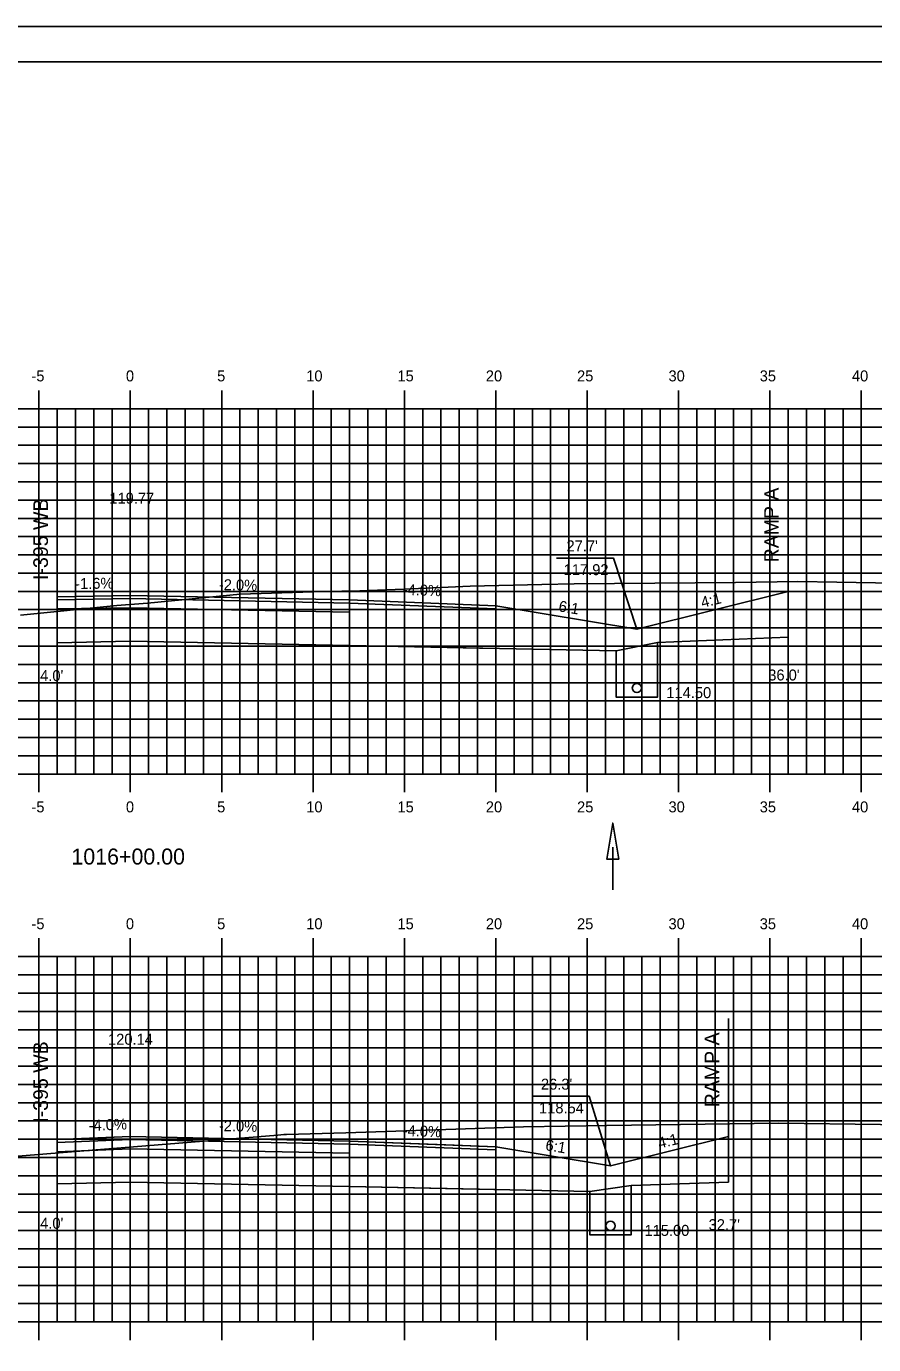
# Model space of a CAD drawing. Extents: x 853069 to 853241, y 365624 to 365734.
# Drawn here: x 853146.4 to 853192.7, y 365661.8 to 365734 of the extents above; entities that cross this region are included whole.
import ezdxf

# ---------------------------------------------------------------- set-up
doc = ezdxf.new("R2010")
doc.units = 0
for name, color, linetype in [('ANNOTATION', 7, 'Continuous'), ('BORDER', 7, 'Continuous'), ('D_Drainage_Ditch_Line', 7, 'Continuous'), ('D_Roadway_Centerline', 7, 'Continuous'), ('D_Roadway_Centerline_Text', 7, 'Continuous'), ('D_Roadway_Edge_Shoulder', 7, 'Continuous'), ('D_Roadway_Edge_TW', 7, 'Continuous'), ('D_Roadway_FinishedGrade', 7, 'Continuous'), ('D_Roadway_Pavement', 7, 'Continuous'), ('D_Roadway_SubGrade', 7, 'Continuous'), ('D_Text_Standard', 7, 'Continuous'), ('Default', 7, 'Continuous'), ('H_V ANNOTATION', 7, 'Continuous'), ('M_Roadway_Centerline', 7, 'Continuous'), ('MAJOR', 7, 'Continuous'), ('MINOR', 7, 'Continuous'), ('PDRAIN', 7, 'Continuous'), ('PLOT BOUNDARY', 7, 'Continuous'), ('S_Roadway_Centerline', 7, 'Continuous')]:
    doc.layers.add(name, color=color, linetype=linetype)

msp = doc.modelspace()

# ---------------------------------------------------------------- linework, layer by layer
at = {"layer": 'ANNOTATION'}
for p, q in [((853188.055, 365703.013), (853188.055, 365700.513)), ((853164.061, 365700.058), (853178.656, 365699.766))]:
    msp.add_line(p, q, dxfattribs=at)
for points in [[(853175.386, 365704.854), (853178.496, 365704.854), (853179.781, 365700.951)], [(853188.055, 365700.513), (853180.906, 365700.229)], [(853174.056, 365675.38), (853177.166, 365675.38), (853178.339, 365671.564)]]:
    msp.add_lwpolyline(points, dxfattribs=at)
at = {"layer": 'BORDER'}
msp.add_lwpolyline([(853077.062, 365627.027), (853237.062, 365627.027), (853237.062, 365732.027), (853077.062, 365732.027)], close=True, dxfattribs=at)
at = {"layer": 'D_Drainage_Ditch_Line'}
msp.add_line((853178.463, 365689.027), (853178.463, 365686.678), dxfattribs=at)
msp.add_lwpolyline([(853178.791, 365688.371), (853178.135, 365688.371), (853178.463, 365690.339)], close=True, dxfattribs=at)
at = {"layer": 'D_Roadway_Centerline'}
for p, q in [((853178.656, 365699.766), (853180.906, 365700.229)), ((853164.061, 365670.431), (853177.214, 365670.168)), ((853177.214, 365670.168), (853179.464, 365670.501))]:
    msp.add_line(p, q, dxfattribs=at)
for points in [[(853172.061, 365702.238), (853179.781, 365700.951), (853188.061, 365703.014)], [(853148.061, 365673.011), (853149.892, 365673.084), (853152.061, 365673.171), (853164.06, 365672.931), (853164.061, 365672.931), (853169.328, 365672.72), (853172.061, 365672.611)], [(853172.061, 365672.611), (853178.339, 365671.564), (853184.796, 365673.174)], [(853184.796, 365670.675), (853179.464, 365670.501)]]:
    msp.add_lwpolyline(points, dxfattribs=at)
at = {"layer": 'D_Roadway_Edge_Shoulder'}
for points in [[(853152.061, 365702.798), (853148.061, 365702.734), (853148.061, 365702.567), (853152.061, 365702.631)], [(853164.061, 365702.558), (853172.061, 365702.238), (853172.061, 365702.071), (853164.061, 365702.391)], [(853152.061, 365673.171), (853148.061, 365673.011), (853148.061, 365672.845), (853152.061, 365673.005)], [(853164.061, 365672.931), (853172.061, 365672.611), (853172.061, 365672.445), (853164.061, 365672.765)]]:
    msp.add_lwpolyline(points, close=True, dxfattribs=at)
at = {"layer": 'D_Roadway_Edge_TW'}
for points in [[(853152.061, 365702.798), (853164.061, 365702.558), (853164.061, 365702.391), (853152.061, 365702.631)], [(853152.061, 365673.171), (853164.061, 365672.931), (853164.061, 365672.765), (853152.061, 365673.005)]]:
    msp.add_lwpolyline(points, close=True, dxfattribs=at)
for points in [[(853164.061, 365702.558), (853164.061, 365702.391)], [(853164.061, 365672.931), (853164.061, 365672.765)]]:
    msp.add_lwpolyline(points, dxfattribs=at)
at = {"layer": 'D_Roadway_FinishedGrade'}
for p, q in [((853152.061, 365702.798), (853152.061, 365702.548)), ((853148.061, 365702.734), (853148.061, 365702.484)), ((853164.061, 365702.558), (853164.061, 365702.308)), ((853172.061, 365702.238), (853172.061, 365701.988)), ((853152.061, 365673.171), (853152.061, 365672.921)), ((853148.061, 365673.011), (853148.061, 365672.761)), ((853164.06, 365672.931), (853164.06, 365672.681)), ((853172.061, 365672.611), (853172.061, 365672.361))]:
    msp.add_line(p, q, dxfattribs=at)
at = {"layer": 'D_Roadway_Pavement'}
for points in [[(853152.061, 365702.631), (853148.061, 365702.567), (853148.061, 365702.067), (853152.061, 365702.131)], [(853152.061, 365702.631), (853164.061, 365702.391), (853164.061, 365701.891), (853152.061, 365702.131)], [(853152.061, 365673.005), (853148.061, 365672.845), (853148.061, 365672.345), (853152.061, 365672.505)], [(853152.061, 365673.005), (853164.061, 365672.765), (853164.061, 365672.265), (853152.061, 365672.505)]]:
    msp.add_lwpolyline(points, close=True, dxfattribs=at)
for points in [[(853164.061, 365702.391), (853164.061, 365701.891)], [(853164.061, 365702.391), (853164.061, 365701.891)], [(853164.061, 365672.765), (853164.061, 365672.265)], [(853164.061, 365672.765), (853164.061, 365672.265)]]:
    msp.add_lwpolyline(points, dxfattribs=at)
at = {"layer": 'D_Roadway_SubGrade'}
for p, q in [((853188.055, 365709.475), (853188.055, 365700.513)), ((853148.061, 365708.638), (853148.061, 365700.218)), ((853184.796, 365679.636), (853184.796, 365670.675)), ((853148.061, 365678.915), (853148.061, 365670.591))]:
    msp.add_line(p, q, dxfattribs=at)
for points in [[(853152.061, 365702.131), (853148.061, 365702.067), (853148.061, 365702.567), (853148.061, 365702.734), (853148.061, 365700.218), (853152.061, 365700.298)], [(853152.061, 365702.131), (853164.061, 365701.891), (853164.061, 365700.058), (853152.061, 365700.298)], [(853164.061, 365701.891), (853164.061, 365702.391), (853172.061, 365702.071), (853172.061, 365702.238), (853172.061, 365699.898), (853164.061, 365700.058)], [(853152.061, 365672.505), (853148.061, 365672.345), (853148.061, 365672.845), (853148.061, 365673.011), (853148.061, 365670.591), (853152.061, 365670.671)], [(853152.061, 365672.505), (853164.061, 365672.265), (853164.061, 365670.431), (853152.061, 365670.671)], [(853164.061, 365672.265), (853164.061, 365672.765), (853172.061, 365672.445), (853172.061, 365672.611), (853172.061, 365670.271), (853164.061, 365670.431)]]:
    msp.add_lwpolyline(points, close=True, dxfattribs=at)
for points in [[(853164.061, 365701.891), (853164.061, 365700.058)], [(853164.061, 365672.265), (853164.061, 365670.431)]]:
    msp.add_lwpolyline(points, dxfattribs=at)
at = {"layer": 'Default'}
msp.add_line((853184.796, 365673.175), (853184.796, 365670.675), dxfattribs=at)
for points in [[(853172.061, 365672.611), (853178.339, 365671.564)], [(853184.796, 365670.675), (853179.464, 365670.501)]]:
    msp.add_lwpolyline(points, dxfattribs=at)
at = {"layer": 'MAJOR'}
for p, q in [((853147.061, 365714.029), (853147.061, 365713.027)), ((853152.061, 365714.029), (853152.061, 365713.027)), ((853157.061, 365714.029), (853157.061, 365713.027)), ((853162.061, 365714.029), (853162.061, 365713.027)), ((853167.061, 365714.029), (853167.061, 365713.027)), ((853172.061, 365714.029), (853172.061, 365713.027)), ((853177.061, 365714.029), (853177.061, 365713.027)), ((853182.061, 365714.029), (853182.061, 365713.027)), ((853187.061, 365714.029), (853187.061, 365713.027)), ((853192.061, 365714.029), (853192.061, 365713.027)), ((853082.061, 365713.027), (853222.061, 365713.027)), ((853082.061, 365713.027), (853222.061, 365713.027)), ((853147.061, 365693.027), (853147.061, 365713.027)), ((853152.061, 365693.027), (853152.061, 365713.027)), ((853157.061, 365693.027), (853157.061, 365713.027)), ((853162.061, 365693.027), (853162.061, 365713.027)), ((853167.061, 365693.027), (853167.061, 365713.027)), ((853172.061, 365693.027), (853172.061, 365713.027)), ((853177.061, 365693.027), (853177.061, 365713.027)), ((853182.061, 365693.027), (853182.061, 365713.027)), ((853187.061, 365693.027), (853187.061, 365713.027)), ((853192.061, 365693.027), (853192.061, 365713.027)), ((853082.061, 365708.027), (853222.061, 365708.027)), ((853082.061, 365703.027), (853222.061, 365703.027)), ((853082.061, 365698.027), (853222.061, 365698.027)), ((853082.061, 365693.027), (853222.061, 365693.027)), ((853082.061, 365693.027), (853222.061, 365693.027)), ((853147.061, 365692.025), (853147.061, 365693.027)), ((853152.061, 365692.025), (853152.061, 365693.027)), ((853157.061, 365692.025), (853157.061, 365693.027)), ((853162.061, 365692.025), (853162.061, 365693.027)), ((853167.061, 365692.025), (853167.061, 365693.027)), ((853172.061, 365692.025), (853172.061, 365693.027)), ((853177.061, 365692.025), (853177.061, 365693.027)), ((853182.061, 365692.025), (853182.061, 365693.027)), ((853187.061, 365692.025), (853187.061, 365693.027)), ((853192.061, 365692.025), (853192.061, 365693.027)), ((853147.061, 365684.029), (853147.061, 365683.027)), ((853152.061, 365684.029), (853152.061, 365683.027)), ((853157.061, 365684.029), (853157.061, 365683.027)), ((853162.061, 365684.029), (853162.061, 365683.027)), ((853167.061, 365684.029), (853167.061, 365683.027)), ((853172.061, 365684.029), (853172.061, 365683.027)), ((853177.061, 365684.029), (853177.061, 365683.027)), ((853182.061, 365684.029), (853182.061, 365683.027)), ((853187.061, 365684.029), (853187.061, 365683.027)), ((853192.061, 365684.029), (853192.061, 365683.027)), ((853082.061, 365683.027), (853222.061, 365683.027)), ((853082.061, 365683.027), (853222.061, 365683.027)), ((853147.061, 365663.027), (853147.061, 365683.027)), ((853152.061, 365663.027), (853152.061, 365683.027)), ((853157.061, 365663.027), (853157.061, 365683.027)), ((853162.061, 365663.027), (853162.061, 365683.027)), ((853167.061, 365663.027), (853167.061, 365683.027)), ((853172.061, 365663.027), (853172.061, 365683.027)), ((853177.061, 365663.027), (853177.061, 365683.027)), ((853182.061, 365663.027), (853182.061, 365683.027)), ((853187.061, 365663.027), (853187.061, 365683.027)), ((853192.061, 365663.027), (853192.061, 365683.027)), ((853082.061, 365678.027), (853222.061, 365678.027)), ((853082.061, 365673.027), (853222.061, 365673.027)), ((853082.061, 365668.027), (853222.061, 365668.027)), ((853082.061, 365663.027), (853222.061, 365663.027)), ((853082.061, 365663.027), (853222.061, 365663.027)), ((853147.061, 365662.025), (853147.061, 365663.027)), ((853152.061, 365662.025), (853152.061, 365663.027)), ((853157.061, 365662.025), (853157.061, 365663.027)), ((853162.061, 365662.025), (853162.061, 365663.027)), ((853167.061, 365662.025), (853167.061, 365663.027)), ((853172.061, 365662.025), (853172.061, 365663.027)), ((853177.061, 365662.025), (853177.061, 365663.027)), ((853182.061, 365662.025), (853182.061, 365663.027)), ((853187.061, 365662.025), (853187.061, 365663.027)), ((853192.061, 365662.025), (853192.061, 365663.027))]:
    msp.add_line(p, q, dxfattribs=at)
at = {"layer": 'MINOR'}
for p, q in [((853148.061, 365693.027), (853148.061, 365713.027)), ((853149.061, 365693.027), (853149.061, 365713.027)), ((853150.061, 365693.027), (853150.061, 365713.027)), ((853151.061, 365693.027), (853151.061, 365713.027)), ((853153.061, 365693.027), (853153.061, 365713.027)), ((853154.061, 365693.027), (853154.061, 365713.027)), ((853155.061, 365693.027), (853155.061, 365713.027)), ((853156.061, 365693.027), (853156.061, 365713.027)), ((853158.061, 365693.027), (853158.061, 365713.027)), ((853159.061, 365693.027), (853159.061, 365713.027)), ((853160.061, 365693.027), (853160.061, 365713.027)), ((853161.061, 365693.027), (853161.061, 365713.027)), ((853163.061, 365693.027), (853163.061, 365713.027)), ((853164.061, 365693.027), (853164.061, 365713.027)), ((853165.061, 365693.027), (853165.061, 365713.027)), ((853166.061, 365693.027), (853166.061, 365713.027)), ((853168.061, 365693.027), (853168.061, 365713.027)), ((853169.061, 365693.027), (853169.061, 365713.027)), ((853170.061, 365693.027), (853170.061, 365713.027)), ((853171.061, 365693.027), (853171.061, 365713.027)), ((853173.061, 365693.027), (853173.061, 365713.027)), ((853174.061, 365693.027), (853174.061, 365713.027)), ((853175.061, 365693.027), (853175.061, 365713.027)), ((853176.061, 365693.027), (853176.061, 365713.027)), ((853178.061, 365693.027), (853178.061, 365713.027)), ((853179.061, 365693.027), (853179.061, 365713.027)), ((853180.061, 365693.027), (853180.061, 365713.027)), ((853181.061, 365693.027), (853181.061, 365713.027)), ((853183.061, 365693.027), (853183.061, 365713.027)), ((853184.061, 365693.027), (853184.061, 365713.027)), ((853185.061, 365693.027), (853185.061, 365713.027)), ((853186.061, 365693.027), (853186.061, 365713.027)), ((853188.061, 365693.027), (853188.061, 365713.027)), ((853189.061, 365693.027), (853189.061, 365713.027)), ((853190.061, 365693.027), (853190.061, 365713.027)), ((853191.061, 365693.027), (853191.061, 365713.027)), ((853082.061, 365712.027), (853222.061, 365712.027)), ((853082.061, 365711.027), (853222.061, 365711.027)), ((853082.061, 365710.027), (853222.061, 365710.027)), ((853082.061, 365709.027), (853222.061, 365709.027)), ((853082.061, 365707.027), (853222.061, 365707.027)), ((853082.061, 365706.027), (853222.061, 365706.027)), ((853082.061, 365705.027), (853222.061, 365705.027)), ((853082.061, 365704.027), (853222.061, 365704.027)), ((853082.061, 365702.027), (853222.061, 365702.027)), ((853082.061, 365701.027), (853222.061, 365701.027)), ((853082.061, 365700.027), (853222.061, 365700.027)), ((853082.061, 365699.027), (853222.061, 365699.027)), ((853082.061, 365697.027), (853222.061, 365697.027)), ((853082.061, 365696.027), (853222.061, 365696.027)), ((853082.061, 365695.027), (853222.061, 365695.027)), ((853082.061, 365694.027), (853222.061, 365694.027)), ((853148.061, 365663.027), (853148.061, 365683.027)), ((853149.061, 365663.027), (853149.061, 365683.027)), ((853150.061, 365663.027), (853150.061, 365683.027)), ((853151.061, 365663.027), (853151.061, 365683.027)), ((853153.061, 365663.027), (853153.061, 365683.027)), ((853154.061, 365663.027), (853154.061, 365683.027)), ((853155.061, 365663.027), (853155.061, 365683.027)), ((853156.061, 365663.027), (853156.061, 365683.027)), ((853158.061, 365663.027), (853158.061, 365683.027)), ((853159.061, 365663.027), (853159.061, 365683.027)), ((853160.061, 365663.027), (853160.061, 365683.027)), ((853161.061, 365663.027), (853161.061, 365683.027)), ((853163.061, 365663.027), (853163.061, 365683.027)), ((853164.061, 365663.027), (853164.061, 365683.027)), ((853165.061, 365663.027), (853165.061, 365683.027)), ((853166.061, 365663.027), (853166.061, 365683.027)), ((853168.061, 365663.027), (853168.061, 365683.027)), ((853169.061, 365663.027), (853169.061, 365683.027)), ((853170.061, 365663.027), (853170.061, 365683.027)), ((853171.061, 365663.027), (853171.061, 365683.027)), ((853173.061, 365663.027), (853173.061, 365683.027)), ((853174.061, 365663.027), (853174.061, 365683.027)), ((853175.061, 365663.027), (853175.061, 365683.027)), ((853176.061, 365663.027), (853176.061, 365683.027)), ((853178.061, 365663.027), (853178.061, 365683.027)), ((853179.061, 365663.027), (853179.061, 365683.027)), ((853180.061, 365663.027), (853180.061, 365683.027)), ((853181.061, 365663.027), (853181.061, 365683.027)), ((853183.061, 365663.027), (853183.061, 365683.027)), ((853184.061, 365663.027), (853184.061, 365683.027)), ((853185.061, 365663.027), (853185.061, 365683.027)), ((853186.061, 365663.027), (853186.061, 365683.027)), ((853188.061, 365663.027), (853188.061, 365683.027)), ((853189.061, 365663.027), (853189.061, 365683.027)), ((853190.061, 365663.027), (853190.061, 365683.027)), ((853191.061, 365663.027), (853191.061, 365683.027)), ((853082.061, 365682.027), (853222.061, 365682.027)), ((853082.061, 365681.027), (853222.061, 365681.027)), ((853082.061, 365680.027), (853222.061, 365680.027)), ((853082.061, 365679.027), (853222.061, 365679.027)), ((853082.061, 365677.027), (853222.061, 365677.027)), ((853082.061, 365676.027), (853222.061, 365676.027)), ((853082.061, 365675.027), (853222.061, 365675.027)), ((853082.061, 365674.027), (853222.061, 365674.027)), ((853082.061, 365672.027), (853222.061, 365672.027)), ((853082.061, 365671.027), (853222.061, 365671.027)), ((853082.061, 365670.027), (853222.061, 365670.027)), ((853082.061, 365669.027), (853222.061, 365669.027)), ((853082.061, 365667.027), (853222.061, 365667.027)), ((853082.061, 365666.027), (853222.061, 365666.027)), ((853082.061, 365665.027), (853222.061, 365665.027)), ((853082.061, 365664.027), (853222.061, 365664.027))]:
    msp.add_line(p, q, dxfattribs=at)
at = {"layer": 'PDRAIN'}
for points in [[(853178.656, 365699.766), (853178.656, 365697.233), (853180.906, 365697.233), (853180.906, 365700.229)], [(853177.214, 365670.168), (853177.214, 365667.786), (853179.464, 365667.786), (853179.464, 365670.501)]]:
    msp.add_lwpolyline(points, dxfattribs=at)
for centre in [(853179.781, 365697.733), (853178.339, 365668.286)]:
    msp.add_circle(centre, 0.25, dxfattribs=at)
at = {"layer": 'PLOT BOUNDARY'}
msp.add_lwpolyline([(853068.968, 365623.968), (853238.968, 365623.968), (853238.968, 365733.968), (853068.968, 365733.968)], close=True, dxfattribs=at)
at = {"layer": 'S_Roadway_Centerline'}
for points in [[(853146.06, 365701.731), (853151.328, 365702.256), (853152.994, 365702.38), (853158.079, 365702.873), (853162.653, 365703.022), (853164.622, 365703.056), (853167.031, 365703.152), (853170.662, 365703.317), (853174.584, 365703.403), (853176.358, 365703.45), (853185.171, 365703.516), (853188.597, 365703.568), (853190.719, 365703.529), (853198.136, 365703.398), (853200.822, 365703.355), (853202.664, 365703.261), (853210.529, 365702.943), (853213.394, 365702.811), (853216.608, 365702.648), (853217.427, 365702.514), (853222.061, 365701.7)], [(853140.919, 365671.697), (853160.13, 365673.253), (853160.468, 365673.285), (853160.611, 365673.288), (853163.848, 365673.373), (853169.878, 365673.576), (853173.583, 365673.698), (853175.863, 365673.749), (853178.131, 365673.789), (853187.551, 365673.905), (853193.111, 365673.835), (853197.409, 365673.744), (853198.878, 365673.668), (853199.61, 365673.64), (853202.439, 365673.501), (853213.429, 365673.011), (853213.719, 365673.043), (853218.8, 365672.06), (853222.061, 365671.378)]]:
    msp.add_lwpolyline(points, dxfattribs=at)

# ---------------------------------------------------------------- texts
at = {"layer": 'ANNOTATION'}
for s, height, rotation, p in [('RAMP A', 0.8, 90, (853187.548, 365704.615)), ('I-395 WB', 0.8, 90, (853147.554, 365703.652)), ("27.7' ", 0.6, 360, (853175.93, 365705.217)), ('117.92', 0.6, 360, (853175.775, 365703.917)), ('-1.6%', 0.6, 0.91657, (853149.05, 365703.15)), ('-2.0%', 0.6, 358.85423, (853156.902, 365703.101)), ('-4.0%', 0.6, 357.70931, (853166.956, 365702.843)), ('4:1', 0.6, 13.99174, (853183.366, 365702.12)), ('6:1', 0.6, 350.53768, (853175.467, 365701.941)), ('I-395 WB', 0.8, 90, (853147.554, 365673.929)), ('RAMP A', 0.8, 90, (853184.289, 365674.777)), ("26.3' ", 0.6, 360, (853174.531, 365675.743)), ('118.54', 0.6, 360, (853174.427, 365674.443)), ('-4.0%', 0.6, 2.29045, (853149.793, 365673.481)), ('-2.0%', 0.6, 358.85423, (853156.904, 365673.474)), ('-4.0%', 0.6, 357.70931, (853166.957, 365673.216)), ('4:1', 0.6, 14.00091, (853181.013, 365672.506)), ('6:1', 0.6, 350.53768, (853174.746, 365672.434))]:
    msp.add_text(s, height=height, rotation=rotation, dxfattribs=at).set_placement(p)
at = {"layer": 'D_Roadway_Centerline'}
for s, p in [('C', (853152.056, 365702.798)), ('L', (853152.061, 365702.79)), ('C', (853152.056, 365673.171)), ('L', (853152.061, 365673.163))]:
    msp.add_text(s, height=0.0146, dxfattribs=at).set_placement(p)
at = {"layer": 'D_Roadway_Centerline_Text'}
for s, p in [('119.77', (853150.916, 365707.83)), ('120.14', (853150.842, 365678.203))]:
    msp.add_text(s, height=0.6, dxfattribs=at).set_placement(p)
at = {"layer": 'D_Text_Standard'}
for s, p in [("4.0'", (853147.127, 365698.116)), ("36.0'", (853186.971, 365698.149)), ('114.50', (853181.394, 365697.183)), ("4.0'", (853147.128, 365668.126)), ('115.00', (853180.197, 365667.736)), ("32.7'", (853183.707, 365668.049))]:
    msp.add_text(s, height=0.6, dxfattribs=at).set_placement(p)
at = {"layer": 'H_V ANNOTATION'}
for s, height, p in [('-5', 0.6, (853146.652, 365714.527)), ('0', 0.6, (853151.821, 365714.527)), ('5', 0.6, (853156.813, 365714.527)), ('10', 0.6, (853161.687, 365714.527)), ('15', 0.6, (853166.679, 365714.527)), ('20', 0.6, (853171.515, 365714.527)), ('25', 0.6, (853176.507, 365714.527)), ('30', 0.6, (853181.51, 365714.527)), ('35', 0.6, (853186.502, 365714.527)), ('40', 0.6, (853191.548, 365714.527)), ('-5', 0.6, (853146.652, 365690.927)), ('0', 0.6, (853151.821, 365690.927)), ('5', 0.6, (853156.813, 365690.927)), ('10', 0.6, (853161.687, 365690.927)), ('15', 0.6, (853166.679, 365690.927)), ('20', 0.6, (853171.515, 365690.927)), ('25', 0.6, (853176.507, 365690.927)), ('30', 0.6, (853181.51, 365690.927)), ('35', 0.6, (853186.502, 365690.927)), ('40', 0.6, (853191.548, 365690.927)), ('1016+00.00', 0.875, (853148.839, 365688.07)), ('-5', 0.6, (853146.652, 365684.527)), ('0', 0.6, (853151.821, 365684.527)), ('5', 0.6, (853156.813, 365684.527)), ('10', 0.6, (853161.687, 365684.527)), ('15', 0.6, (853166.679, 365684.527)), ('20', 0.6, (853171.515, 365684.527)), ('25', 0.6, (853176.507, 365684.527)), ('30', 0.6, (853181.51, 365684.527)), ('35', 0.6, (853186.502, 365684.527)), ('40', 0.6, (853191.548, 365684.527))]:
    msp.add_text(s, height=height, dxfattribs=at).set_placement(p)
at = {"layer": 'M_Roadway_Centerline'}
for s, p in [('C', (853170.657, 365703.317)), ('L', (853170.662, 365703.31)), ('C', (853173.578, 365673.698)), ('L', (853173.583, 365673.691))]:
    msp.add_text(s, height=0.0146, dxfattribs=at).set_placement(p)

doc.saveas('drawing.dxf')
